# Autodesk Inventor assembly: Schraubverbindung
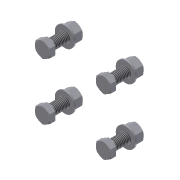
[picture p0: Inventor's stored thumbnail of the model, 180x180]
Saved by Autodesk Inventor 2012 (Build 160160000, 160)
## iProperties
Company: CAD-Verlag
Created: 2004-12
Part Number: Schraubverbindung
Document SubType Name: Assembly
Designer: jukr
Manufacturer: Standard
Standards Organization: Custom
Author: Jürgen Kronas
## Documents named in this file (4)
- C:\DemoDaten2012\CAD Daten\Daten Vault 2012 Inventor\Kapitel 4\Anschlag\Normteile\Schraubverbindung.iam
- C:\DemoDaten2012\CAD Daten\Daten Vault 2012 Inventor\Kapitel 4\Anschlag\Normteile\I4017A000Q9FLB_MIR.ipt
- C:\DemoDaten2012\CAD Daten\Daten Vault 2012 Inventor\Kapitel 4\Anschlag\Normteile\D125_2000RI1XB_MIR.ipt
- C:\DemoDaten2012\CAD Daten\Daten Vault 2012 Inventor\Kapitel 4\Anschlag\Normteile\I4032000YBW6B_MIR.ipt
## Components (12 placed, 3 different names)
1. I4017A000Q9FLB_MIR:1
2. D125_2000RI1XB_MIR:1
3. I4032000YBW6B_MIR:1
4. I4017A000Q9FLB_MIR:2
5. D125_2000RI1XB_MIR:2
6. I4032000YBW6B_MIR:2
7. I4017A000Q9FLB_MIR:3
8. D125_2000RI1XB_MIR:3
9. I4032000YBW6B_MIR:3
10. I4017A000Q9FLB_MIR:4
11. D125_2000RI1XB_MIR:4
12. I4032000YBW6B_MIR:4
